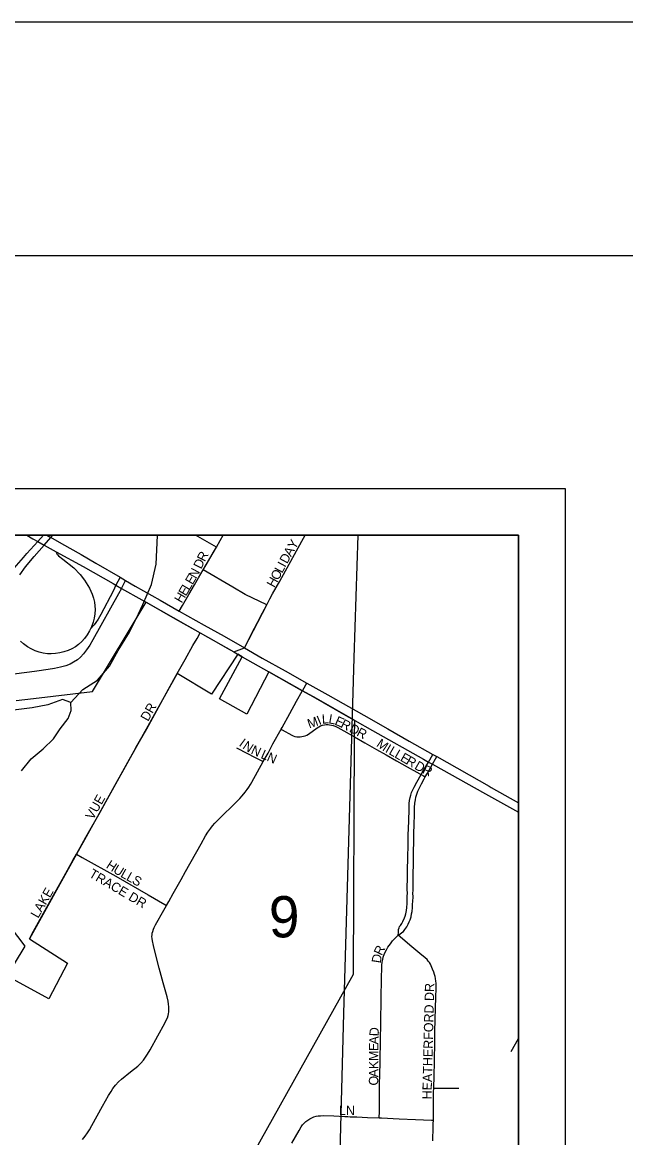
# Model space of a CAD drawing. Extents: x -5.6 to 34, y 0 to 22.
# Drawn here: x 7.835 to 9.13, y 19.608 to 22 of the extents above; entities that cross this region are included whole.
import ezdxf

# ---------------------------------------------------------------- set-up
doc = ezdxf.new("R2010")
doc.units = 0
for name, color, linetype in [('GM_X_City_Street', 7, 'Continuous'), ('GM_X_City_Street_Text', 7, 'Continuous'), ('GM_X_Corporation', 7, 'Continuous'), ('GM_X_Interchange_Ramps', 7, 'Continuous'), ('GM_X_Interstate_Route', 7, 'Continuous'), ('GM_X_Minor_Lake', 7, 'Continuous'), ('GM_X_Minor_River', 7, 'Continuous'), ('GM_X_Section', 7, 'Continuous'), ('GM_X_Section_Text', 7, 'Continuous'), ('GM_X_Township', 7, 'Continuous'), ('GM_X_Township_Road', 7, 'Continuous'), ('GM_X_Township_Subdivision', 7, 'Continuous'), ('GM_X_Township_Subdivision_Text', 7, 'Continuous'), ('GM_X_US_Route', 7, 'Continuous'), ('SH_Border', 7, 'Continuous'), ('SH_Cut_Line', 7, 'Continuous'), ('SH_Data', 7, 'Continuous')]:
    doc.layers.add(name, color=color, linetype=linetype)

msp = doc.modelspace()

# ---------------------------------------------------------------- linework, layer by layer
at = {"layer": 'GM_X_City_Street'}
for points in [[(8.1717, 20.7372), (8.1787, 20.7491), (8.1927, 20.773), (8.2049, 20.7938), (8.2133, 20.8082), (8.2233, 20.8255)], [(8.3905, 20.4839), (8.3926, 20.4877), (8.4089, 20.5175), (8.4236, 20.5437), (8.4358, 20.5654), (8.4363, 20.5664)], [(8.3522, 20.4146), (8.3624, 20.4327), (8.373, 20.4522), (8.3905, 20.4839)], [(8.3905, 20.4839), (8.3926, 20.4827), (8.4133, 20.4711), (8.4167, 20.4697), (8.4203, 20.4686), (8.424, 20.4678), (8.4277, 20.4674), (8.4314, 20.4674), (8.4351, 20.4679), (8.4387, 20.4687), (8.4423, 20.4699), (8.4457, 20.4714), (8.449, 20.4732), (8.4522, 20.4753), (8.4647, 20.4849), (8.468, 20.4872), (8.4716, 20.4892), (8.4754, 20.4909), (8.4793, 20.4923), (8.4833, 20.4932), (8.4874, 20.4938), (8.4915, 20.4939), (8.4943, 20.4936), (8.4984, 20.4929), (8.5024, 20.4918), (8.5062, 20.4904), (8.5123, 20.4875), (8.525, 20.4805), (8.5479, 20.4674)], [(8.2951, 20.444), (8.3184, 20.4316), (8.3336, 20.4236), (8.3522, 20.4146)], [(8.1446, 20.106), (8.1493, 20.1144), (8.159, 20.1316), (8.1757, 20.1614), (8.1854, 20.1785), (8.2188, 20.2381), (8.2286, 20.2551), (8.2335, 20.2628), (8.2394, 20.2713), (8.2434, 20.2764), (8.2486, 20.2822), (8.2622, 20.2963), (8.2895, 20.3229), (8.3016, 20.335), (8.3072, 20.3413), (8.3137, 20.3491), (8.3176, 20.3545), (8.3212, 20.3596), (8.3246, 20.365), (8.3275, 20.3701), (8.3522, 20.4146)], [(7.9513, 20.2161), (7.9637, 20.209), (8.0356, 20.1684), (8.105, 20.1288), (8.1409, 20.1082), (8.1446, 20.106)], [(7.9644, 19.6042), (7.9703, 19.6114), (7.975, 19.6179), (7.9792, 19.6246), (7.9845, 19.6338), (8.0074, 19.6752), (8.0137, 19.6867), (8.0201, 19.6981), (8.0255, 19.7071), (8.0297, 19.7136), (8.035, 19.7208), (8.0413, 19.7273), (8.0481, 19.7333), (8.0675, 19.7489), (8.0828, 19.7615), (8.0893, 19.7674), (8.0951, 19.7738), (8.0998, 19.7802), (8.1041, 19.787), (8.1094, 19.7961), (8.1259, 19.8261), (8.1412, 19.8537), (8.1442, 19.8596), (8.1464, 19.8646), (8.1481, 19.8697), (8.149, 19.8737), (8.1496, 19.8778), (8.1498, 19.8832), (8.1496, 19.8887), (8.149, 19.894), (8.1478, 19.9006), (8.1457, 19.9096), (8.1374, 19.9401), (8.1287, 19.9717), (8.1231, 19.9933), (8.1164, 20.02), (8.1142, 20.0302), (8.1135, 20.0352), (8.1133, 20.039), (8.1135, 20.0427), (8.114, 20.0464), (8.1149, 20.0501), (8.1165, 20.0549), (8.118, 20.0584), (8.121, 20.064), (8.1391, 20.096), (8.1446, 20.106)]]:
    msp.add_lwpolyline(points, dxfattribs=at)
at = {"layer": 'GM_X_Corporation'}
for points in [[(7.8222, 20.5454), (7.859, 20.5495), (7.9857, 20.5645), (8.1009, 20.7561), (8.2167, 20.6906), (8.289, 20.6496), (8.3118, 20.6581), (8.3598, 20.7506), (8.3132, 20.7731), (8.2869, 20.7887), (8.2234, 20.8255), (8.2516, 20.8742), (8.2067, 20.9), (4.0671, 20.9)], [(8.2463, 19.4221), (8.5459, 19.9586), (8.5479, 20.4674), (8.5488, 20.5027), (8.4666, 20.5494), (8.4363, 20.5663), (8.3645, 20.6066), (8.3171, 20.5165), (8.2585, 20.5492), (8.3071, 20.6394), (8.298, 20.6445), (8.2412, 20.5587), (8.1676, 20.6031), (7.9513, 20.2161), (7.8503, 20.0343), (7.9319, 19.982), (7.8921, 19.9053), (7.8147, 19.9475)], [(7.8186, 19.9805), (7.8412, 20.0189), (7.6656, 20.2498)]]:
    msp.add_lwpolyline(points, dxfattribs=at)
at = {"layer": 'GM_X_Interchange_Ramps'}
for points in [[(7.8296, 20.8152), (7.8422, 20.8321), (7.8607, 20.8543), (7.8821, 20.8788), (7.8966, 20.8953), (7.9006, 20.9)], [(7.9077, 20.8645), (7.9085, 20.8622), (7.9092, 20.86), (7.9099, 20.8588), (7.911, 20.8576), (7.9131, 20.8557), (7.9219, 20.8488), (7.946, 20.8298), (7.959, 20.8157), (7.9686, 20.8037), (7.9796, 20.7862), (7.9847, 20.7737), (7.9878, 20.765), (7.99, 20.7561), (7.9911, 20.7483), (7.9915, 20.7404), (7.991, 20.7313), (7.9895, 20.7222), (7.9872, 20.7133), (7.9835, 20.7035), (7.9814, 20.6992), (7.9795, 20.6952), (7.9742, 20.6861), (7.9687, 20.6787), (7.9626, 20.6718), (7.9558, 20.6657), (7.9495, 20.6609), (7.9415, 20.6564), (7.9332, 20.6525), (7.9245, 20.6496), (7.9155, 20.6474), (7.9064, 20.6461), (7.8972, 20.6456), (7.8893, 20.6459), (7.8802, 20.6472), (7.8713, 20.6493), (7.8626, 20.6522), (7.8542, 20.656), (7.8462, 20.6606), (7.8378, 20.6668), (7.8309, 20.673)], [(8.0449, 20.8097), (8.0404, 20.801), (8.0361, 20.7926), (8.0298, 20.7802), (8.0035, 20.7299), (7.9976, 20.7199), (7.9932, 20.713), (7.9893, 20.7081), (7.9814, 20.6992)], [(8.048, 20.7859), (8.0517, 20.7929), (8.0569, 20.8028)]]:
    msp.add_lwpolyline(points, dxfattribs=at)
at = {"layer": 'GM_X_Interstate_Route'}
for points in [[(7.8448, 20.8604), (7.8683, 20.8865), (7.8804, 20.9)], [(7.4684, 20.3909), (7.5571, 20.5067), (7.5917, 20.5513), (7.6684, 20.6497), (7.7087, 20.6999), (7.7512, 20.7517), (7.7928, 20.8009), (7.8377, 20.8524), (7.8448, 20.8604)]]:
    msp.add_lwpolyline(points, dxfattribs=at)
at = {"layer": 'GM_X_Minor_Lake'}
msp.add_lwpolyline([(7.8333, 20.3945), (7.8544, 20.4207), (7.8802, 20.442), (7.902, 20.4634), (7.9167, 20.4848), (7.9337, 20.5071), (7.9403, 20.5238), (7.939, 20.5415), (7.9215, 20.5473), (7.8902, 20.5365), (7.8566, 20.5297), (7.8103, 20.5238)], dxfattribs=at)
at = {"layer": 'GM_X_Minor_River'}
for points in [[(7.939, 20.5415), (7.9648, 20.5692), (7.9962, 20.5888), (8.0221, 20.619), (8.0409, 20.6524), (8.0654, 20.6922), (8.0793, 20.7209), (8.094, 20.7512), (8.1122, 20.7942), (8.1223, 20.8382), (8.1255, 20.8991), (8.1256, 20.9)], [(8.555, 20.9), (8.5465, 20.6373), (8.5247, 19.8744), (8.5123, 19.4145), (8.5029, 18.8743), (8.495, 18.4512), (8.4884, 17.9407), (8.486, 17.5111), (8.4872, 17.3019), (8.4824, 16.7441), (8.4793, 16.0837), (8.4766, 15.7495)]]:
    msp.add_lwpolyline(points, dxfattribs=at)
at = {"layer": 'GM_X_Section'}
msp.add_lwpolyline([(8.9, 18.906), (8.9, 20.9), (7.5006, 20.9), (7.4578, 18.9294)], close=True, dxfattribs=at)
at = {"layer": 'GM_X_Township'}
msp.add_lwpolyline([(3.0636, 14.1), (8.9, 14.1), (8.9, 20.9), (2.1, 20.9), (2.1, 16.9108), (2.7242, 16.8707), (3.1388, 16.8616), (3.0745, 14.7121)], close=True, dxfattribs=at)
at = {"layer": 'GM_X_Township_Road'}
msp.add_line((8.8844, 19.793), (8.9, 19.8205), dxfattribs=at)
msp.add_lwpolyline([(8.4363, 20.5664), (8.4435, 20.579), (8.4457, 20.5829)], dxfattribs=at)
at = {"layer": 'GM_X_Township_Subdivision'}
for points in [[(8.2516, 20.8742), (8.2594, 20.8883), (8.2664, 20.9)], [(8.3598, 20.7506), (8.3665, 20.7638), (8.3721, 20.7741), (8.3875, 20.8016), (8.4154, 20.8523), (8.4385, 20.8936), (8.442, 20.9)], [(8.2233, 20.8255), (8.2316, 20.8397), (8.2432, 20.8597), (8.2516, 20.8742)], [(8.3119, 20.6581), (8.3273, 20.6882), (8.3397, 20.7124), (8.3505, 20.7332), (8.3598, 20.7506)], [(8.1676, 20.6031), (8.1846, 20.6334), (8.2012, 20.6631), (8.2101, 20.6787), (8.2167, 20.6906)], [(7.9513, 20.2161), (7.9717, 20.2526), (8.002, 20.3063), (8.0301, 20.3568), (8.079, 20.4437), (8.1021, 20.4849), (8.1326, 20.54), (8.149, 20.57), (8.1676, 20.6031)], [(8.5479, 20.4674), (8.57, 20.4547), (8.5951, 20.4405), (8.6157, 20.429), (8.6385, 20.416), (8.6613, 20.4032), (8.6884, 20.3879), (8.691, 20.3865)], [(8.7066, 20.4135), (8.7162, 20.43)], [(8.691, 20.3865), (8.6935, 20.3909), (8.7066, 20.4135)], [(8.6999, 20.3814), (8.7048, 20.3896), (8.7154, 20.4086)], [(8.7154, 20.4086), (8.722, 20.4204), (8.7247, 20.4252)], [(8.6416, 20.0423), (8.6421, 20.048), (8.6428, 20.0546), (8.6436, 20.0578), (8.6449, 20.0607), (8.6466, 20.0631), (8.6493, 20.0671), (8.6519, 20.0718), (8.6554, 20.0791), (8.6568, 20.0829), (8.6583, 20.0881), (8.6597, 20.0948), (8.6604, 20.1014), (8.6612, 20.1104), (8.6614, 20.1183), (8.6614, 20.125), (8.6615, 20.1329), (8.6612, 20.1396), (8.6615, 20.1685), (8.6619, 20.1842), (8.6622, 20.2052), (8.6629, 20.2393), (8.6634, 20.2564), (8.6643, 20.2865), (8.665, 20.3128), (8.6656, 20.3245), (8.6663, 20.3309), (8.6673, 20.3372), (8.6686, 20.3421), (8.6706, 20.3482), (8.6731, 20.3541), (8.676, 20.3599), (8.6818, 20.3701), (8.691, 20.3865)], [(8.691, 20.3865), (8.696, 20.3836), (8.6999, 20.3814)], [(8.6416, 20.0423), (8.6456, 20.0446), (8.6499, 20.0477), (8.6529, 20.0503), (8.6546, 20.0521), (8.6564, 20.0546), (8.6603, 20.0604), (8.6633, 20.0661), (8.6655, 20.0707), (8.6674, 20.0754), (8.6693, 20.0816), (8.6707, 20.0878), (8.6715, 20.0929), (8.6722, 20.1012), (8.6728, 20.1083), (8.6733, 20.1148), (8.6736, 20.1239), (8.6735, 20.1332), (8.674, 20.1375), (8.674, 20.1741), (8.6744, 20.1938), (8.6748, 20.2187), (8.6751, 20.245), (8.6754, 20.2634), (8.676, 20.2765), (8.6765, 20.3041), (8.677, 20.316), (8.6777, 20.3253), (8.6786, 20.3326), (8.6798, 20.3385), (8.6817, 20.3449), (8.684, 20.3512), (8.6873, 20.3585), (8.6915, 20.3668), (8.6974, 20.3772), (8.6999, 20.3814)], [(7.8503, 20.0343), (7.8594, 20.0508), (7.8771, 20.0829), (7.9059, 20.1345), (7.9251, 20.1689), (7.9435, 20.2022), (7.9513, 20.2161)], [(8.6011, 19.6503), (8.6014, 19.6638), (8.6016, 19.6728), (8.6019, 19.6898), (8.602, 19.7081), (8.602, 19.7199), (8.6024, 19.7461), (8.6029, 19.7669), (8.6033, 19.7878), (8.6035, 19.802), (8.6038, 19.8233), (8.6043, 19.8462), (8.6045, 19.8599), (8.6048, 19.8746), (8.605, 19.8861), (8.6053, 19.9009), (8.6056, 19.9173), (8.606, 19.9382), (8.6063, 19.9544), (8.6064, 19.9688), (8.6069, 19.978), (8.6076, 19.9846), (8.6085, 19.9897), (8.6099, 19.9948), (8.612, 20.001), (8.614, 20.0059), (8.6164, 20.0106), (8.6198, 20.0162), (8.625, 20.0238), (8.6296, 20.0302), (8.6332, 20.0337), (8.6416, 20.0423)], [(8.7181, 19.7138), (8.7183, 19.7196), (8.7187, 19.7345), (8.7194, 19.7761), (8.7201, 19.8094), (8.7207, 19.8364), (8.7213, 19.8601), (8.722, 19.8872), (8.7225, 19.9077), (8.723, 19.9295), (8.7233, 19.9339), (8.723, 19.939), (8.7226, 19.9434), (8.7216, 19.9495), (8.7209, 19.9535), (8.7199, 19.9575), (8.7182, 19.9626), (8.7157, 19.9693), (8.7128, 19.9762), (8.7111, 19.9799), (8.7089, 19.9834), (8.7064, 19.9867), (8.7037, 19.9898), (8.6997, 19.9934), (8.6884, 20.0025), (8.6713, 20.0169), (8.6416, 20.0423)], [(8.7173, 19.6455), (8.7174, 19.6611), (8.7174, 19.6821), (8.7177, 19.6952), (8.7179, 19.7057), (8.7181, 19.7138)], [(8.7181, 19.7138), (8.7205, 19.7138), (8.7314, 19.7138), (8.7405, 19.7137), (8.751, 19.7137), (8.7589, 19.7137), (8.7721, 19.7137)], [(8.4133, 19.596), (8.429, 19.6233), (8.4337, 19.631), (8.4367, 19.6351), (8.44, 19.639), (8.4437, 19.6425), (8.4477, 19.6456), (8.4519, 19.6484), (8.4564, 19.6506), (8.4611, 19.6524), (8.466, 19.6538), (8.4697, 19.6545), (8.4748, 19.655), (8.4812, 19.6551), (8.5035, 19.6545), (8.527, 19.6534), (8.5336, 19.653), (8.5388, 19.6529), (8.5532, 19.6522), (8.5756, 19.6511), (8.6011, 19.6503)], [(8.6011, 19.6503), (8.6057, 19.6501), (8.6438, 19.6486), (8.6792, 19.6469), (8.7134, 19.6457), (8.7173, 19.6455)], [(8.7161, 19.6014), (8.7164, 19.6122), (8.7167, 19.6197), (8.717, 19.6297), (8.7172, 19.6374), (8.7173, 19.6455)]]:
    msp.add_lwpolyline(points, dxfattribs=at)
at = {"layer": 'GM_X_US_Route'}
msp.add_line((7.845, 20.9), (7.858, 20.8925), dxfattribs=at)
for points in [[(7.858, 20.8925), (7.8683, 20.8865), (7.8821, 20.8788), (7.9012, 20.868), (7.9077, 20.8645), (7.9658, 20.8327), (8.0298, 20.7962), (8.0361, 20.7926), (8.048, 20.7859)], [(7.8881, 20.9), (7.8966, 20.8953), (7.9009, 20.893), (7.9191, 20.8825), (7.9612, 20.8583), (7.9931, 20.84), (8.0449, 20.8097), (8.0569, 20.8028), (8.0771, 20.791), (8.1307, 20.7603), (8.1717, 20.7372), (8.2257, 20.7067), (8.2681, 20.6831), (8.3119, 20.6581), (8.3499, 20.6366), (8.3991, 20.609), (8.4457, 20.5829), (8.4907, 20.5576), (8.5684, 20.5137), (8.6198, 20.4845), (8.6654, 20.4586), (8.7162, 20.43), (8.7247, 20.4252), (8.837, 20.3615), (8.8416, 20.3589), (8.9, 20.326)], [(8.048, 20.7859), (8.0418, 20.7742), (7.9865, 20.6755), (7.9797, 20.664), (7.9731, 20.6538), (7.9664, 20.6452), (7.9597, 20.6383), (7.9533, 20.633), (7.9453, 20.6276), (7.9381, 20.6236), (7.9285, 20.6196), (7.9174, 20.6168), (7.9045, 20.6141), (7.8909, 20.6117), (7.8663, 20.6086), (7.8611, 20.608), (7.783, 20.5975)], [(8.048, 20.7859), (8.0915, 20.7611), (8.1009, 20.7561)], [(8.1009, 20.7561), (8.1634, 20.7207)], [(8.1634, 20.7207), (8.2167, 20.6906), (8.2346, 20.6805), (8.2814, 20.6541), (8.289, 20.6496)], [(8.289, 20.6496), (8.3071, 20.6394)], [(8.3071, 20.6394), (8.3645, 20.6066)], [(8.3645, 20.6066), (8.4338, 20.5678), (8.4363, 20.5664), (8.4588, 20.5538), (8.5296, 20.5134), (8.5488, 20.5027)], [(8.5488, 20.5027), (8.5864, 20.4814), (8.6962, 20.4194), (8.7066, 20.4135), (8.7154, 20.4086), (8.8292, 20.3453), (8.9, 20.3058)]]:
    msp.add_lwpolyline(points, dxfattribs=at)
at = {"layer": 'SH_Border'}
msp.add_lwpolyline([(1.5, 21.5), (33.5, 21.5), (33.5, 0.5), (1.5, 0.5)], close=True, dxfattribs=at)
at = {"layer": 'SH_Cut_Line'}
msp.add_lwpolyline([(0, 0), (34, 0), (34, 22), (0, 22)], close=True, dxfattribs=at)
at = {"layer": 'SH_Data'}
for p, q in [((2, 21), (9, 21)), ((9, 21), (9, 14)), ((2.1, 20.9), (8.9, 20.9)), ((8.9, 20.9), (8.9, 14.1))]:
    msp.add_line(p, q, dxfattribs=at)

# ---------------------------------------------------------------- texts
at = {"layer": 'GM_X_City_Street_Text'}
for s, rotation, p in [('R', 63.4344, (8.2268, 20.8418)), ('D', 63.4233, (8.219, 20.826)), ('E', 59.5466, (8.2005, 20.7923)), ('N', 62.09, (8.2081, 20.8053)), ('E', 59.3461, (8.1861, 20.768)), ('L', 59.3267, (8.1933, 20.7802)), ('H', 59.3361, (8.1771, 20.7529)), ('M', 18.9187, (8.4509, 20.4853)), ('I', 22.6208, (8.4722, 20.4926)), ('L', 3.7995, (8.4786, 20.4956)), ('L', 350.0031, (8.4914, 20.4966)), ('E', 335.5244, (8.504, 20.4946)), ('R', 332.5988, (8.5166, 20.4888)), ('D', 332.3402, (8.5353, 20.4791)), ('R', 332.3489, (8.5509, 20.4709)), ('I', 323.4711, (8.2987, 20.4495)), ('N', 325.998, (8.3065, 20.4437)), ('N', 335.4729, (8.3242, 20.4321)), ('L', 336.3565, (8.3454, 20.4226)), ('N', 336.3813, (8.3583, 20.4169)), ('H', 327.3344, (8.0134, 20.1875)), ('U', 328.6004, (8.0286, 20.1777)), ('TRACE DR', 329.6217, (7.9765, 20.1684)), ('L', 330.6268, (8.0443, 20.1682)), ('L', 330.7518, (8.0566, 20.1612)), ('S', 330.7464, (8.0689, 20.1544))]:
    msp.add_text(s, height=0.02, rotation=rotation, dxfattribs=at).set_placement(p)
at = {"layer": 'GM_X_Section_Text'}
msp.add_text('9', height=0.0884, rotation=0, dxfattribs=at).set_placement((8.3642, 20.0375))
at = {"layer": 'GM_X_Township_Subdivision_Text'}
for s, rotation, p in [('Y', 59.561, (8.4205, 20.8679)), ('D', 61.4698, (8.4034, 20.8374)), ('A', 60.0897, (8.4117, 20.8527)), ('I', 61.6578, (8.3992, 20.8296)), ('O', 61.6825, (8.3842, 20.8017)), ('L', 61.6752, (8.3926, 20.8172)), ('H', 61.6756, (8.3759, 20.7862)), ('DR', 60.6435, (8.1049, 20.4994)), ('M', 325.6228, (8.5936, 20.4484)), ('I', 330.1717, (8.6125, 20.4356)), ('L', 330.2394, (8.6201, 20.4312)), ('L', 330.245, (8.6324, 20.4242)), ('E', 330.2314, (8.6446, 20.4172)), ('R', 330.2303, (8.6568, 20.4102)), ('D', 330.2379, (8.6752, 20.3997)), ('R', 334.7774, (8.6919, 20.3902)), ('VUE', 60.7988, (7.9869, 20.2882)), ('LAKE', 60.0679, (7.869, 20.0771)), ('D', 80.8251, (8.6042, 19.9811)), ('R', 64.7821, (8.6065, 19.997)), ('HEATHERFORD DR', 88.625, (8.7133, 19.6898)), ('D', 87.5949, (8.5999, 19.825)), ('E', 89.0438, (8.599, 19.7935)), ('A', 87.7697, (8.5992, 19.8075)), ('M', 89.9818, (8.599, 19.7725)), ('K', 89.9781, (8.5989, 19.7549)), ('O', 89.9781, (8.5989, 19.7197)), ('A', 89.9928, (8.5989, 19.7373)), ('LN', 0, (8.5147, 19.6565))]:
    msp.add_text(s, height=0.02, rotation=rotation, dxfattribs=at).set_placement(p)

doc.saveas('drawing.dxf')
